(* Logix 5000 project; controller Test vendor 1 type 14 code 92 rev 33.11; software revision 33.00; part 3 of 4 *)
(* tags used below, declared in another part *)
   WLS : Banner_WLS_v4;
   Port_Data : Banner_IOL_Port_v4;
   Port : INT;   // Port Number that device is plugged into.
   Type : SINT;   // 0 = WLS27, 1 = WLS15, 2 = WLF
   Local_Control : DINT;
   Command_Being_Processed : BOOL;
   Update_Archive : BOOL;
   Index_Write_Inprocess : DINT;
   Index_Write_Control : DINT;
   Inprocess_Index : DINT;
   SW_Index : DINT;
   LT_Index : DINT;
   IndexW2 : DINT;
   LTW_Index : DINT;
   G_Index : DINT;
   IndexW3 : DINT;
(* Banner_WLS_Param_v4, continued *)

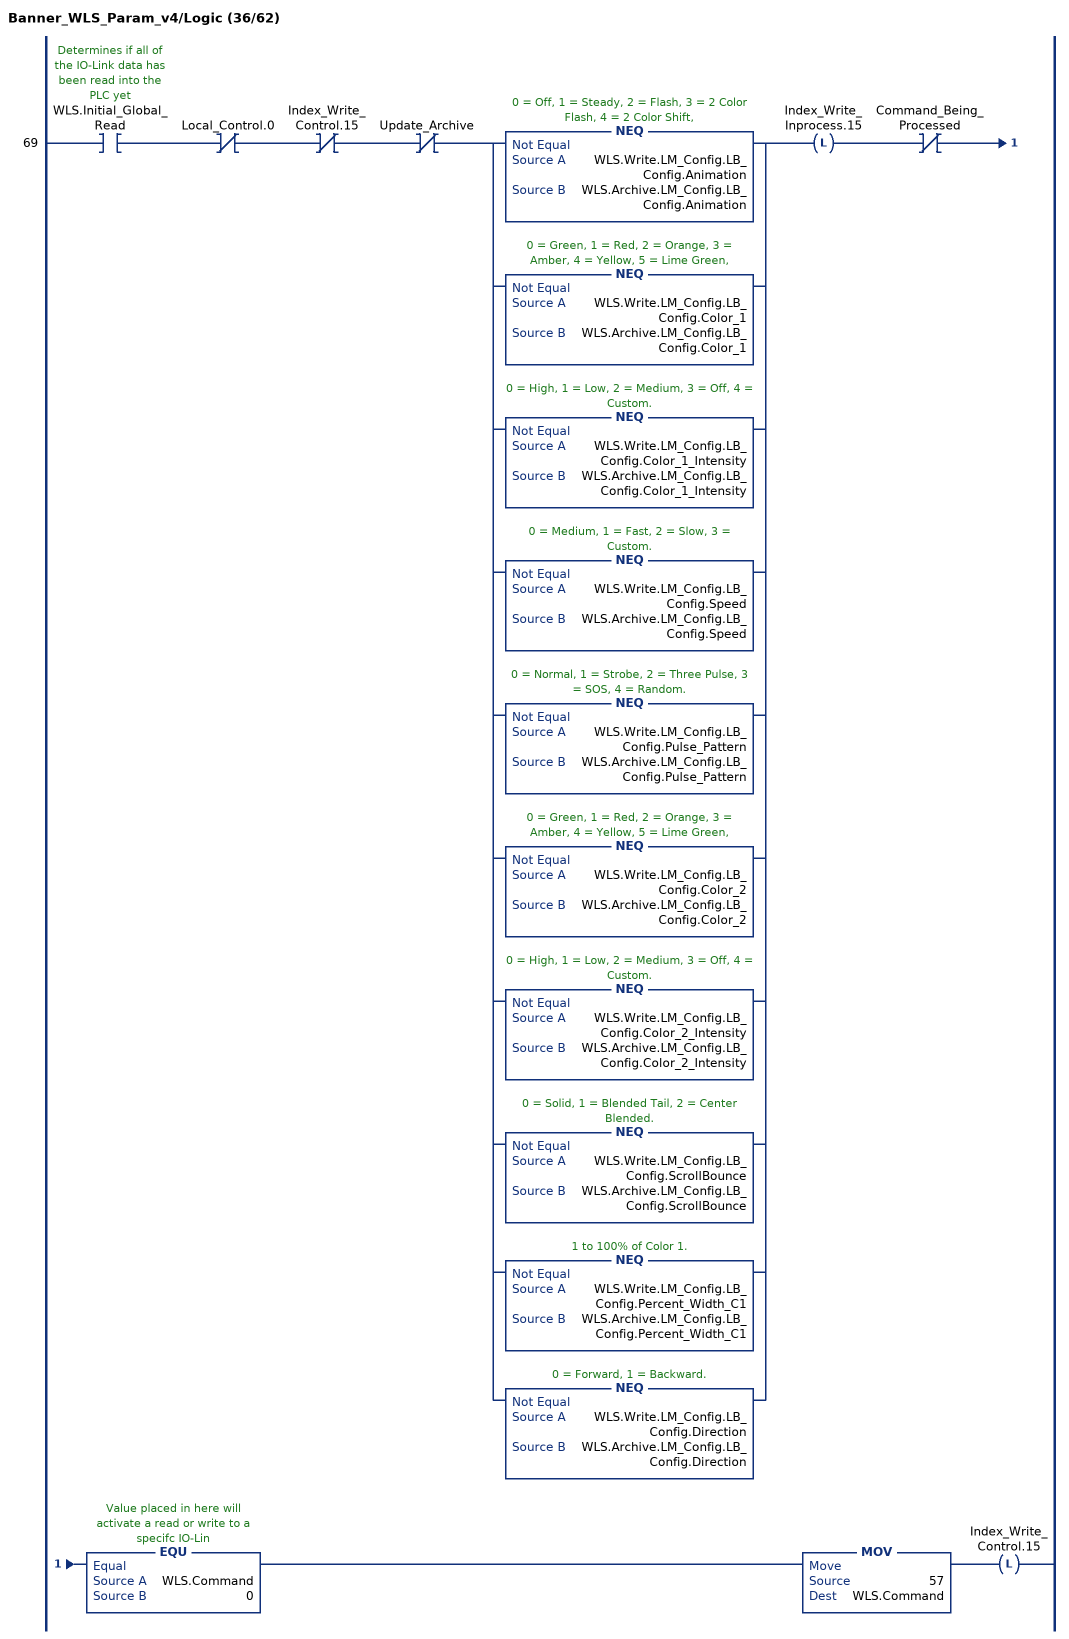
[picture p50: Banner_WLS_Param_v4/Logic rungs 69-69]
   69: XIC(WLS.Initial_Global_Read)XIO(Local_Control.0)XIO(Index_Write_Control.15)XIO(Update_Archive)[NEQ(WLS.Write.LM_Config.LB_Config.Animation,WLS.Archive.LM_Config.LB_Config.Animation) ,NEQ(WLS.Write.LM_Config.LB_Config.Color_1,WLS.Archive.LM_Config.LB_Config.Color_1) ,NEQ(WLS.Write.LM_Config.LB_Config.Color_1_Intensity,WLS.Archive.LM_Config.LB_Config.Color_1_Intensity) ,NEQ(WLS.Write.LM_Config.LB_Config.Speed,WLS.Archive.LM_Config.LB_Config.Speed) ,NEQ(WLS.Write.LM_Config.LB_Config.Pulse_Pattern,WLS.Archive.LM_Config.LB_Config.Pulse_Pattern) ,NEQ(WLS.Write.LM_Config.LB_Config.Color_2,WLS.Archive.LM_Config.LB_Config.Color_2) ,NEQ(WLS.Write.LM_Config.LB_Config.Color_2_Intensity,WLS.Archive.LM_Config.LB_Config.Color_2_Intensity) ,NEQ(WLS.Write.LM_Config.LB_Config.ScrollBounce,WLS.Archive.LM_Config.LB_Config.ScrollBounce) ,NEQ(WLS.Write.LM_Config.LB_Config.Percent_Width_C1,WLS.Archive.LM_Config.LB_Config.Percent_Width_C1) ,NEQ(WLS.Write.LM_Config.LB_Config.Direction,WLS.Archive.LM_Config.LB_Config.Direction) ]OTL(Index_Write_Inprocess.15)XIO(Command_Being_Processed)EQU(WLS.Command,0)MOV(57,WLS.Command)OTL(Index_Write_Control.15);
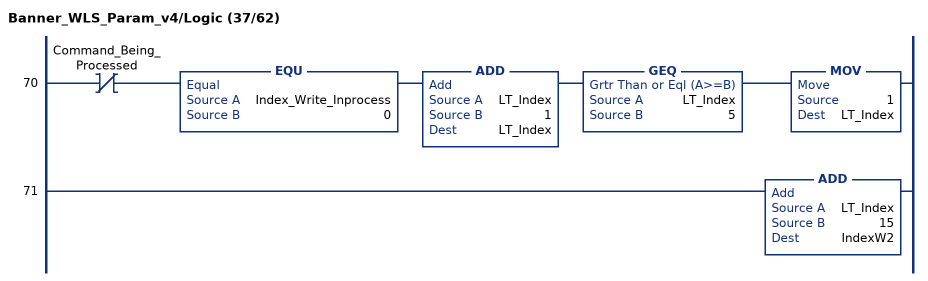
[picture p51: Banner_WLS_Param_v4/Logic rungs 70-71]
   70: XIO(Command_Being_Processed)EQU(Index_Write_Inprocess,0)ADD(LT_Index,1,LT_Index)GEQ(LT_Index,5)MOV(1,LT_Index);
   71: ADD(LT_Index,15,IndexW2);
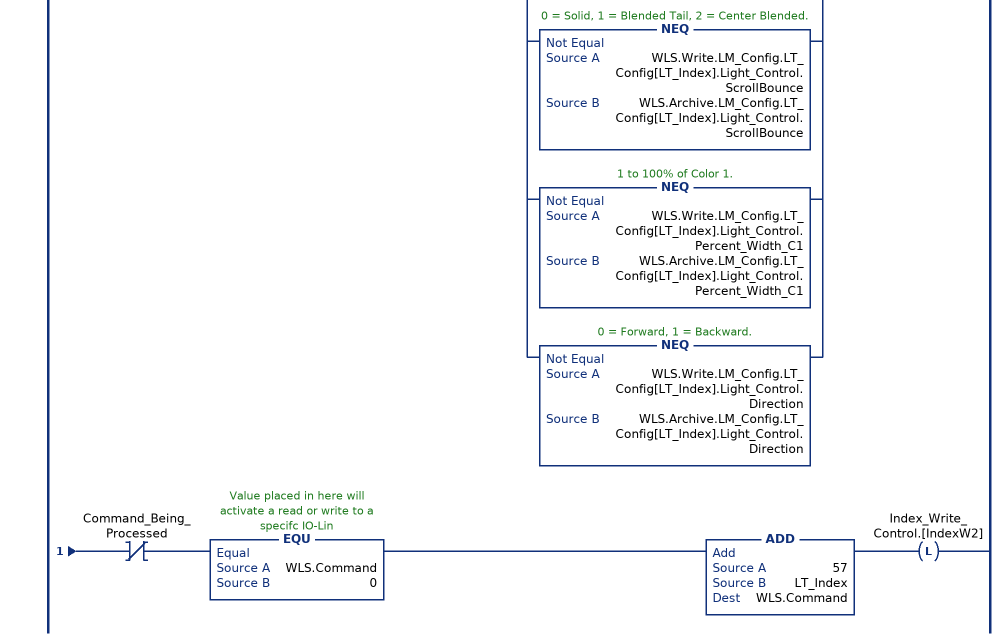
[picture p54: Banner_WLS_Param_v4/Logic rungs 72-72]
   72: XIC(WLS.Initial_Global_Read)XIO(Local_Control.0)XIO(Index_Write_Control.[IndexW2])XIO(Update_Archive)[NEQ(WLS.Write.LM_Config.LT_Config[LT_Index].Threshold_Enable,WLS.Archive.LM_Config.LT_Config[LT_Index].Threshold_Enable) ,NEQ(WLS.Write.LM_Config.LT_Config[LT_Index].Threshold_Value,WLS.Archive.LM_Config.LT_Config[LT_Index].Threshold_Value) ,NEQ(WLS.Write.LM_Config.LT_Config[LT_Index].Threshold_Comparison,WLS.Archive.LM_Config.LT_Config[LT_Index].Threshold_Comparison) ,NEQ(WLS.Write.LM_Config.LT_Config[LT_Index].Threshold_Override,WLS.Archive.LM_Config.LT_Config[LT_Index].Threshold_Override) ,NEQ(WLS.Write.LM_Config.LT_Config[LT_Index].Light_Control.Animation,WLS.Archive.LM_Config.LT_Config[LT_Index].Light_Control.Animation) ,NEQ(WLS.Write.LM_Config.LT_Config[LT_Index].Light_Control.Color_1,WLS.Archive.LM_Config.LT_Config[LT_Index].Light_Control.Color_1) ,NEQ(WLS.Write.LM_Config.LT_Config[LT_Index].Light_Control.Color_1_Intensity,WLS.Archive.LM_Config.LT_Config[LT_Index].Light_Control.Color_1_Intensity) ,NEQ(WLS.Write.LM_Config.LT_Config[LT_Index].Light_Control.Speed,WLS.Archive.LM_Config.LT_Config[LT_Index].Light_Control.Speed) ,NEQ(WLS.Write.LM_Config.LT_Config[LT_Index].Light_Control.Pulse_Pattern,WLS.Archive.LM_Config.LT_Config[LT_Index].Light_Control.Pulse_Pattern) ,NEQ(WLS.Write.LM_Config.LT_Config[LT_Index].Light_Control.Color_2,WLS.Archive.LM_Config.LT_Config[LT_Index].Light_Control.Color_2) ,NEQ(WLS.Write.LM_Config.LT_Config[LT_Index].Light_Control.Color_2_Intensity,WLS.Archive.LM_Config.LT_Config[LT_Index].Light_Control.Color_2_Intensity) ,NEQ(WLS.Write.LM_Config.LT_Config[LT_Index].Light_Control.ScrollBounce,WLS.Archive.LM_Config.LT_Config[LT_Index].Light_Control.ScrollBounce) ,NEQ(WLS.Write.LM_Config.LT_Config[LT_Index].Light_Control.Percent_Width_C1,WLS.Archive.LM_Config.LT_Config[LT_Index].Light_Control.Percent_Width_C1) ,NEQ(WLS.Write.LM_Config.LT_Config[LT_Index].Light_Control.Direction,WLS.Archive.LM_Config.LT_Config[LT_Index].Light_Control.Direction) ]OTL(Index_Write_Inprocess.[IndexW2])XIO(Command_Being_Processed)EQU(WLS.Command,0)ADD(57,LT_Index,WLS.Command)OTL(Index_Write_Control.[IndexW2]);
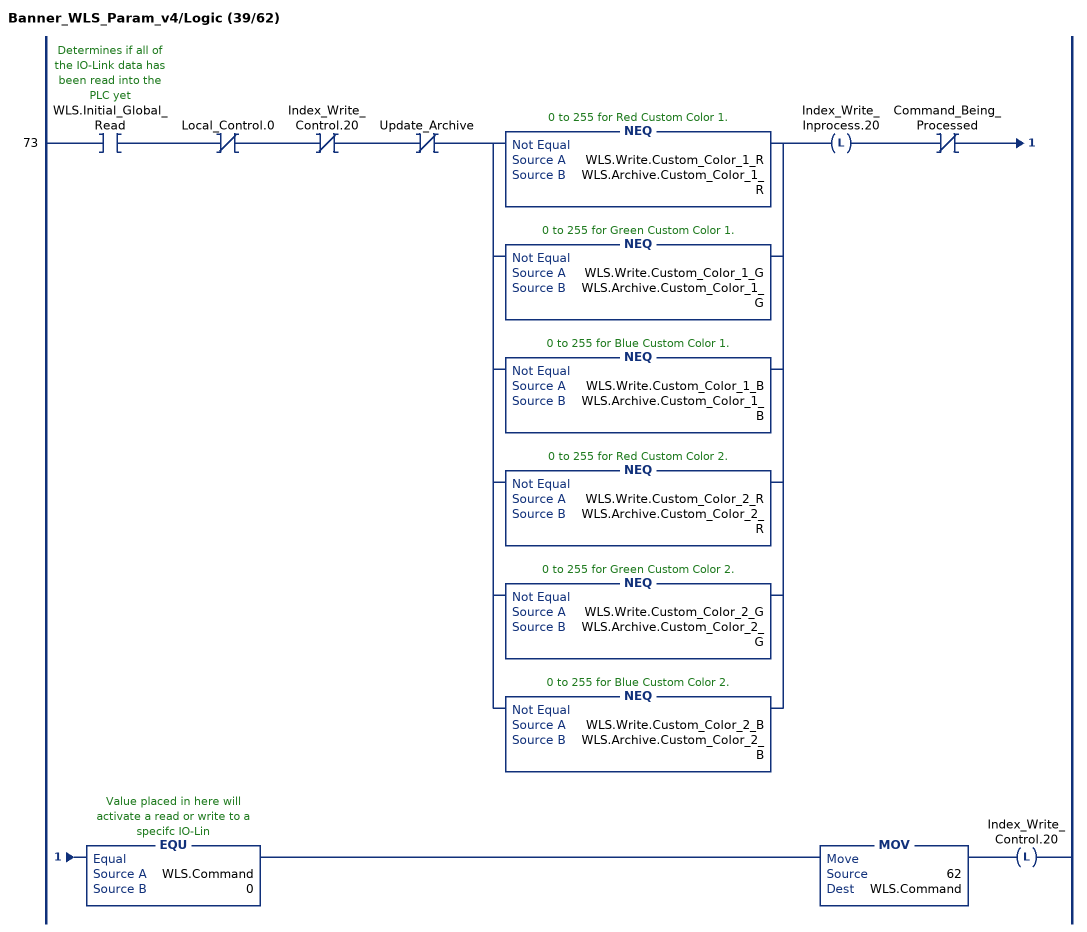
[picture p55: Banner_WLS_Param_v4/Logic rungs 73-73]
   73: XIC(WLS.Initial_Global_Read)XIO(Local_Control.0)XIO(Index_Write_Control.20)XIO(Update_Archive)[NEQ(WLS.Write.Custom_Color_1_R,WLS.Archive.Custom_Color_1_R) ,NEQ(WLS.Write.Custom_Color_1_G,WLS.Archive.Custom_Color_1_G) ,NEQ(WLS.Write.Custom_Color_1_B,WLS.Archive.Custom_Color_1_B) ,NEQ(WLS.Write.Custom_Color_2_R,WLS.Archive.Custom_Color_2_R) ,NEQ(WLS.Write.Custom_Color_2_G,WLS.Archive.Custom_Color_2_G) ,NEQ(WLS.Write.Custom_Color_2_B,WLS.Archive.Custom_Color_2_B) ]OTL(Index_Write_Inprocess.20)XIO(Command_Being_Processed)EQU(WLS.Command,0)MOV(62,WLS.Command)OTL(Index_Write_Control.20);
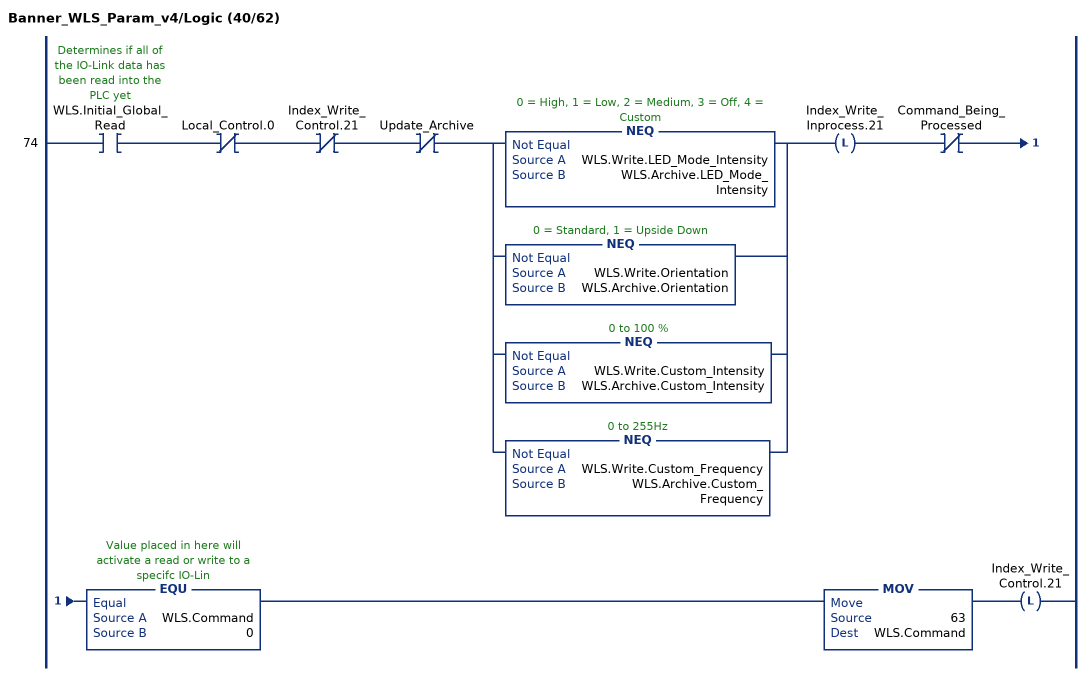
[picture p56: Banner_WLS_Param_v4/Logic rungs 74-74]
   74: XIC(WLS.Initial_Global_Read)XIO(Local_Control.0)XIO(Index_Write_Control.21)XIO(Update_Archive)[NEQ(WLS.Write.LED_Mode_Intensity,WLS.Archive.LED_Mode_Intensity) ,NEQ(WLS.Write.Orientation,WLS.Archive.Orientation) ,NEQ(WLS.Write.Custom_Intensity,WLS.Archive.Custom_Intensity) ,NEQ(WLS.Write.Custom_Frequency,WLS.Archive.Custom_Frequency) ]OTL(Index_Write_Inprocess.21)XIO(Command_Being_Processed)EQU(WLS.Command,0)MOV(63,WLS.Command)OTL(Index_Write_Control.21);
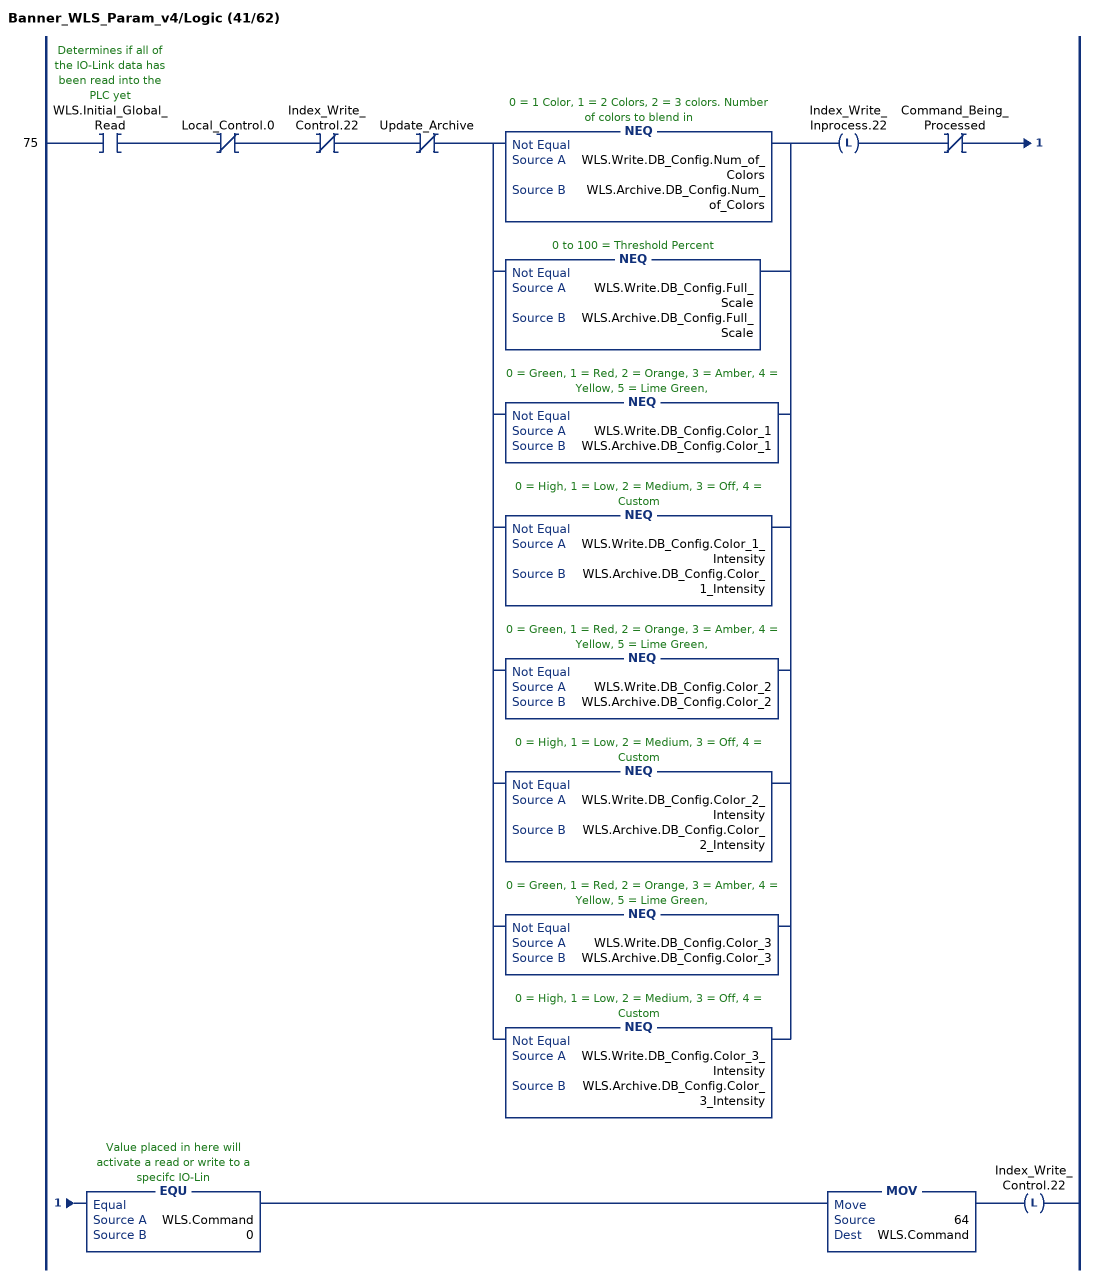
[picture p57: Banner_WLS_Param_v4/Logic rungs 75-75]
   75: XIC(WLS.Initial_Global_Read)XIO(Local_Control.0)XIO(Index_Write_Control.22)XIO(Update_Archive)[NEQ(WLS.Write.DB_Config.Num_of_Colors,WLS.Archive.DB_Config.Num_of_Colors) ,NEQ(WLS.Write.DB_Config.Full_Scale,WLS.Archive.DB_Config.Full_Scale) ,NEQ(WLS.Write.DB_Config.Color_1,WLS.Archive.DB_Config.Color_1) ,NEQ(WLS.Write.DB_Config.Color_1_Intensity,WLS.Archive.DB_Config.Color_1_Intensity) ,NEQ(WLS.Write.DB_Config.Color_2,WLS.Archive.DB_Config.Color_2) ,NEQ(WLS.Write.DB_Config.Color_2_Intensity,WLS.Archive.DB_Config.Color_2_Intensity) ,NEQ(WLS.Write.DB_Config.Color_3,WLS.Archive.DB_Config.Color_3) ,NEQ(WLS.Write.DB_Config.Color_3_Intensity,WLS.Archive.DB_Config.Color_3_Intensity) ]OTL(Index_Write_Inprocess.22)XIO(Command_Being_Processed)EQU(WLS.Command,0)MOV(64,WLS.Command)OTL(Index_Write_Control.22);
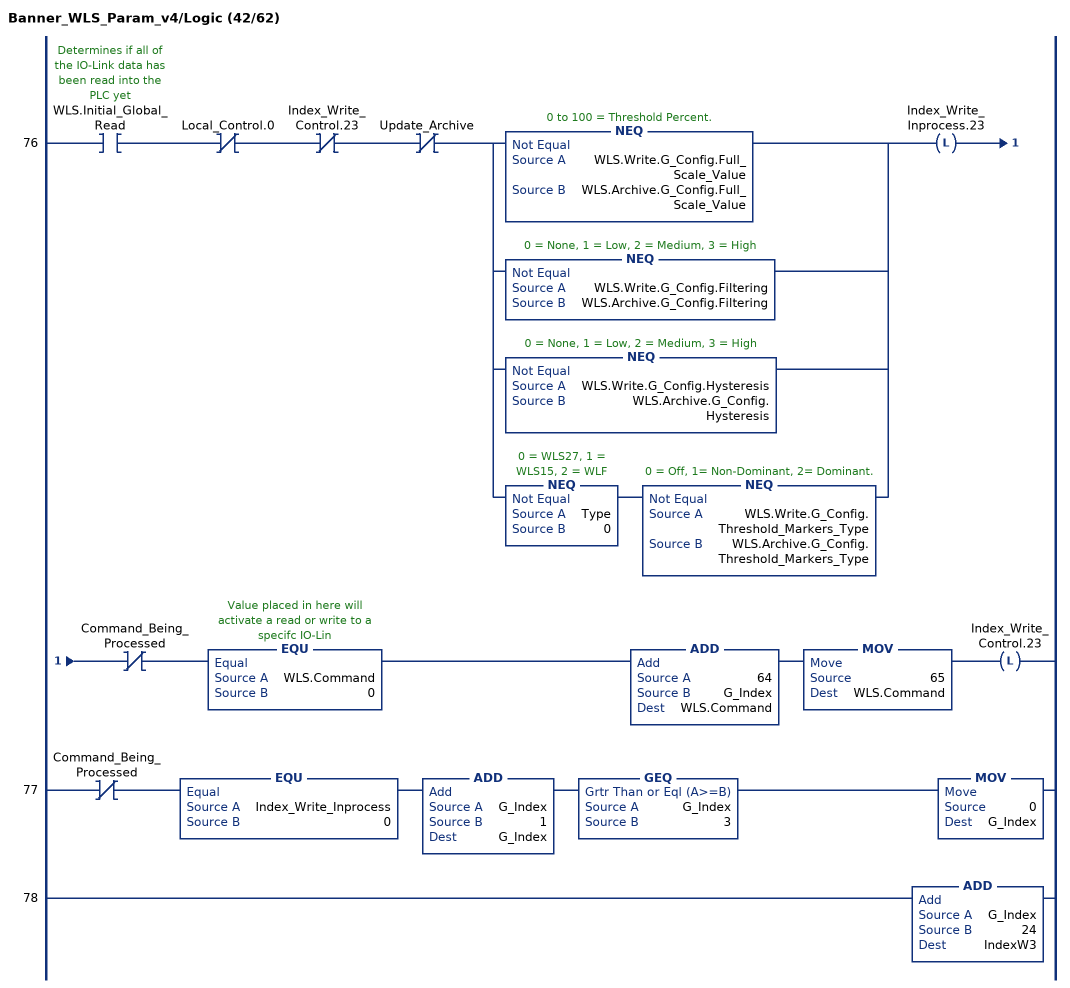
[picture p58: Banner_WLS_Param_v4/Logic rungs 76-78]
   76: XIC(WLS.Initial_Global_Read)XIO(Local_Control.0)XIO(Index_Write_Control.23)XIO(Update_Archive)[NEQ(WLS.Write.G_Config.Full_Scale_Value,WLS.Archive.G_Config.Full_Scale_Value) ,NEQ(WLS.Write.G_Config.Filtering,WLS.Archive.G_Config.Filtering) ,NEQ(WLS.Write.G_Config.Hysteresis,WLS.Archive.G_Config.Hysteresis) ,NEQ(Type,0) NEQ(WLS.Write.G_Config.Threshold_Markers_Type,WLS.Archive.G_Config.Threshold_Markers_Type) ]OTL(Index_Write_Inprocess.23)XIO(Command_Being_Processed)EQU(WLS.Command,0)ADD(64,G_Index,WLS.Command)MOV(65,WLS.Command)OTL(Index_Write_Control.23);
   77: XIO(Command_Being_Processed)EQU(Index_Write_Inprocess,0)ADD(G_Index,1,G_Index)GEQ(G_Index,3)MOV(0,G_Index);
   78: ADD(G_Index,24,IndexW3);
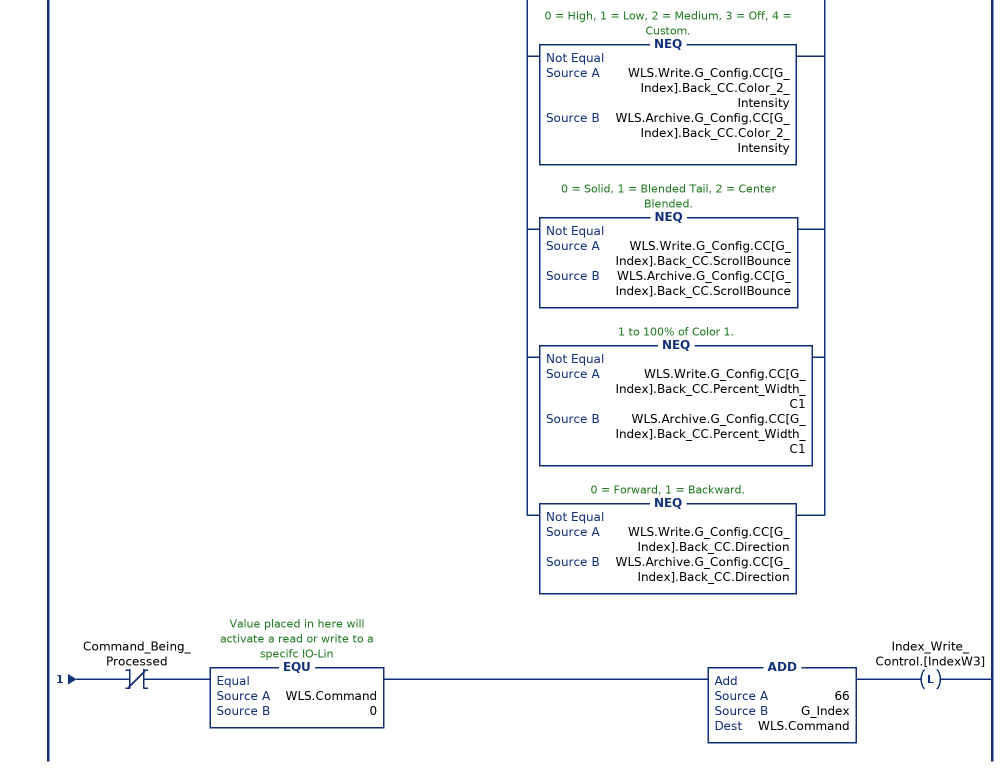
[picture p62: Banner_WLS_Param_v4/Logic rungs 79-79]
   79: XIC(WLS.Initial_Global_Read)XIO(Local_Control.0)XIO(Index_Write_Control.[IndexW3])XIO(Update_Archive)[NEQ(WLS.Write.G_Config.CC[G_Index].Threshold_Enable,WLS.Archive.G_Config.CC[G_Index].Threshold_Enable) ,NEQ(WLS.Write.G_Config.CC[G_Index].Threshold_Value_Percent,WLS.Archive.G_Config.CC[G_Index].Threshold_Value_Percent) ,NEQ(WLS.Write.G_Config.CC[G_Index].Threshold_Comparison,WLS.Archive.G_Config.CC[G_Index].Threshold_Comparison) ,NEQ(WLS.Write.G_Config.CC[G_Index].Percent_Width_of_Main_Segment,WLS.Archive.G_Config.CC[G_Index].Percent_Width_of_Main_Segment) ,NEQ(WLS.Write.G_Config.CC[G_Index].Main_CC.Animation,WLS.Archive.G_Config.CC[G_Index].Main_CC.Animation) ,NEQ(WLS.Write.G_Config.CC[G_Index].Main_CC.Color_1,WLS.Archive.G_Config.CC[G_Index].Main_CC.Color_1) ,NEQ(WLS.Write.G_Config.CC[G_Index].Main_CC.Color_1_Intensity,WLS.Archive.G_Config.CC[G_Index].Main_CC.Color_1_Intensity) ,NEQ(WLS.Write.G_Config.CC[G_Index].Main_CC.Speed,WLS.Archive.G_Config.CC[G_Index].Main_CC.Speed) ,NEQ(WLS.Write.G_Config.CC[G_Index].Main_CC.Pulse_Pattern,WLS.Archive.G_Config.CC[G_Index].Main_CC.Pulse_Pattern) ,NEQ(WLS.Write.G_Config.CC[G_Index].Main_CC.Color_2,WLS.Archive.G_Config.CC[G_Index].Main_CC.Color_2) ,NEQ(WLS.Write.G_Config.CC[G_Index].Main_CC.Color_2_Intensity,WLS.Archive.G_Config.CC[G_Index].Main_CC.Color_2_Intensity) ,NEQ(WLS.Write.G_Config.CC[G_Index].Main_CC.ScrollBounce,WLS.Archive.G_Config.CC[G_Index].Main_CC.ScrollBounce) ,NEQ(WLS.Write.G_Config.CC[G_Index].Main_CC.Percent_Width_C1,WLS.Archive.G_Config.CC[G_Index].Main_CC.Percent_Width_C1) ,NEQ(WLS.Write.G_Config.CC[G_Index].Main_CC.Direction,WLS.Archive.G_Config.CC[G_Index].Main_CC.Direction) ,NEQ(WLS.Write.G_Config.CC[G_Index].Back_CC.Animation,WLS.Archive.G_Config.CC[G_Index].Back_CC.Animation) ,NEQ(WLS.Write.G_Config.CC[G_Index].Back_CC.Color_1,WLS.Archive.G_Config.CC[G_Index].Back_CC.Color_1) ,NEQ(WLS.Write.G_Config.CC[G_Index].Back_CC.Color_1_Intensity,WLS.Archive.G_Config.CC[G_Index].Back_CC.Color_1_Intensity) ,NEQ(WLS.Write.G_Config.CC[G_Index].Back_CC.Speed,WLS.Archive.G_Config.CC[0].Back_CC.Speed) ,NEQ(WLS.Write.G_Config.CC[G_Index].Back_CC.Pulse_Pattern,WLS.Archive.G_Config.CC[G_Index].Back_CC.Pulse_Pattern) ,NEQ(WLS.Write.G_Config.CC[G_Index].Back_CC.Color_2,WLS.Archive.G_Config.CC[G_Index].Back_CC.Color_2) ,NEQ(WLS.Write.G_Config.CC[G_Index].Back_CC.Color_2_Intensity,WLS.Archive.G_Config.CC[G_Index].Back_CC.Color_2_Intensity) ,NEQ(WLS.Write.G_Config.CC[G_Index].Back_CC.ScrollBounce,WLS.Archive.G_Config.CC[G_Index].Back_CC.ScrollBounce) ,NEQ(WLS.Write.G_Config.CC[G_Index].Back_CC.Percent_Width_C1,WLS.Archive.G_Config.CC[G_Index].Back_CC.Percent_Width_C1) ,NEQ(WLS.Write.G_Config.CC[G_Index].Back_CC.Direction,WLS.Archive.G_Config.CC[G_Index].Back_CC.Direction) ]OTL(Index_Write_Inprocess.[IndexW3])XIO(Command_Being_Processed)EQU(WLS.Command,0)ADD(66,G_Index,WLS.Command)OTL(Index_Write_Control.[IndexW3]);
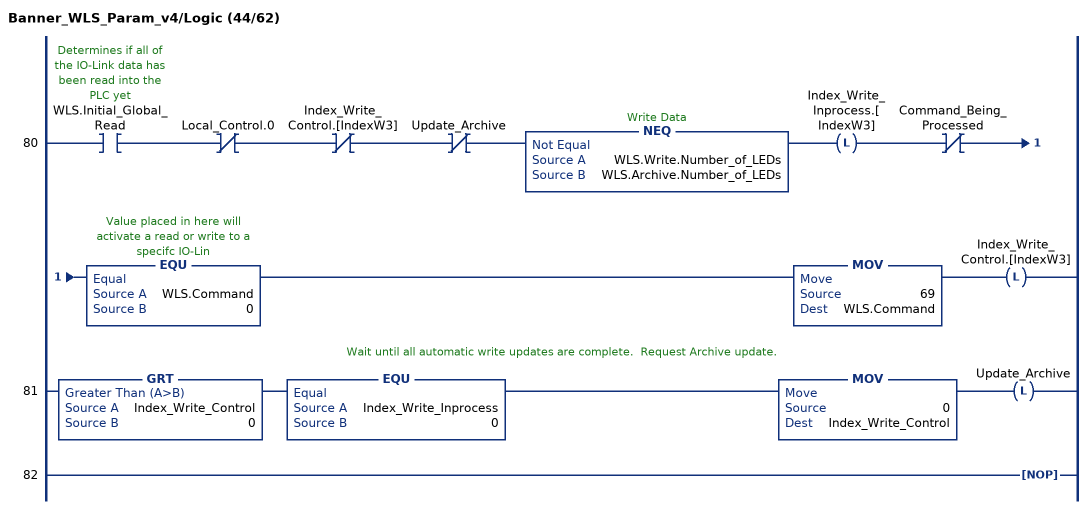
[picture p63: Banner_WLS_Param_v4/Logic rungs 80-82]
   80: XIC(WLS.Initial_Global_Read)XIO(Local_Control.0)XIO(Index_Write_Control.[IndexW3])XIO(Update_Archive)NEQ(WLS.Write.Number_of_LEDs,WLS.Archive.Number_of_LEDs)OTL(Index_Write_Inprocess.[IndexW3])XIO(Command_Being_Processed)EQU(WLS.Command,0)MOV(69,WLS.Command)OTL(Index_Write_Control.[IndexW3]);
   // Wait until all automatic write updates are complete.  Request Archive update.
   81: GRT(Index_Write_Control,0)EQU(Index_Write_Inprocess,0)MOV(0,Index_Write_Control)OTL(Update_Archive);
   82: NOP();
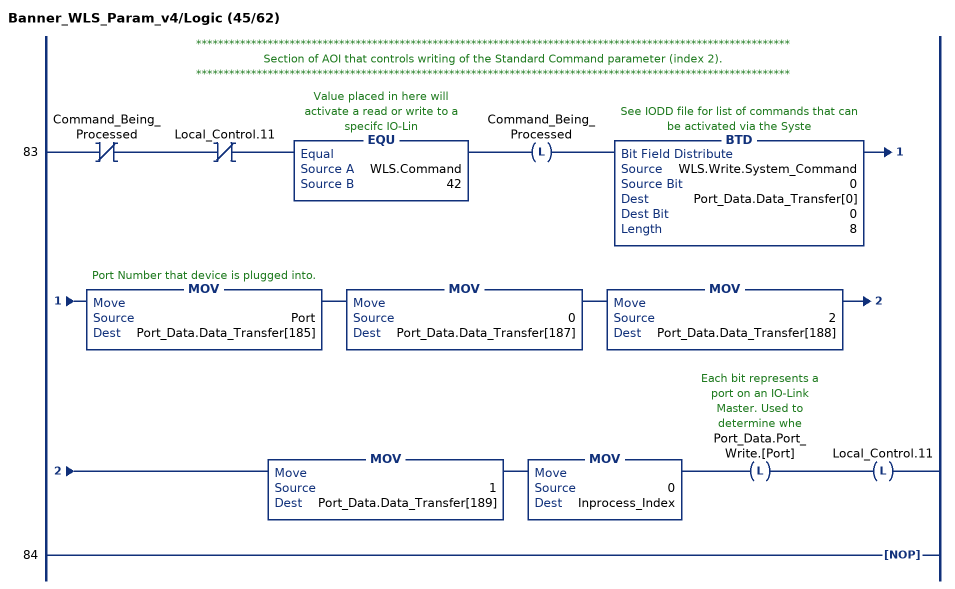
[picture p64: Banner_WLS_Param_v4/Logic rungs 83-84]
   // ************************************************************************************************************
   // Section of AOI that controls writing of the Standard Command parameter (index 2).
   // ************************************************************************************************************
   83: XIO(Command_Being_Processed)XIO(Local_Control.11)EQU(WLS.Command,42)OTL(Command_Being_Processed)BTD(WLS.Write.System_Command,0,Port_Data.Data_Transfer[0],0,8)MOV(Port,Port_Data.Data_Transfer[185])MOV(0,Port_Data.Data_Transfer[187])MOV(2,Port_Data.Data_Transfer[188])MOV(1,Port_Data.Data_Transfer[189])MOV(0,Inprocess_Index)OTL(Port_Data.Port_Write.[Port])OTL(Local_Control.11);
   84: NOP();
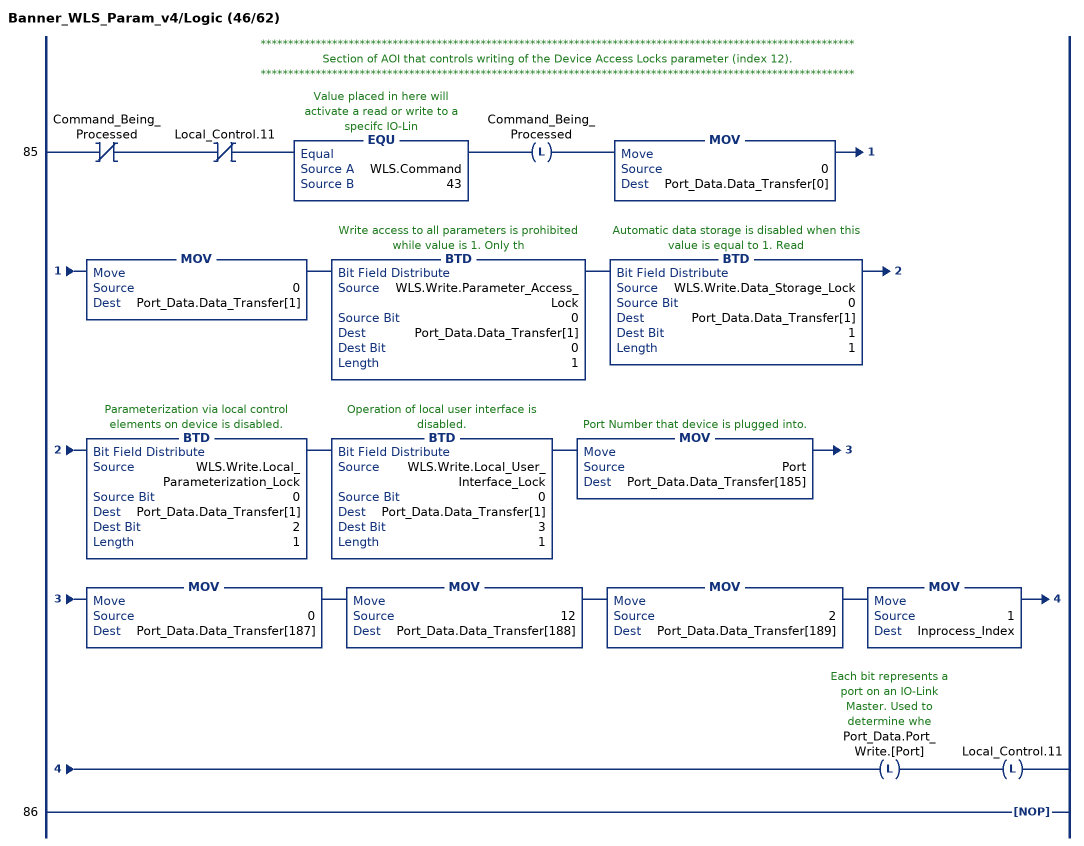
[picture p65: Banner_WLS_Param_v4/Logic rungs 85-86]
   // ************************************************************************************************************
   // Section of AOI that controls writing of the Device Access Locks parameter (index 12).
   // ************************************************************************************************************
   85: XIO(Command_Being_Processed)XIO(Local_Control.11)EQU(WLS.Command,43)OTL(Command_Being_Processed)MOV(0,Port_Data.Data_Transfer[0])MOV(0,Port_Data.Data_Transfer[1])BTD(WLS.Write.Parameter_Access_Lock,0,Port_Data.Data_Transfer[1],0,1)BTD(WLS.Write.Data_Storage_Lock,0,Port_Data.Data_Transfer[1],1,1)BTD(WLS.Write.Local_Parameterization_Lock,0,Port_Data.Data_Transfer[1],2,1)BTD(WLS.Write.Local_User_Interface_Lock,0,Port_Data.Data_Transfer[1],3,1)MOV(Port,Port_Data.Data_Transfer[185])MOV(0,Port_Data.Data_Transfer[187])MOV(12,Port_Data.Data_Transfer[188])MOV(2,Port_Data.Data_Transfer[189])MOV(1,Inprocess_Index)OTL(Port_Data.Port_Write.[Port])OTL(Local_Control.11);
   86: NOP();
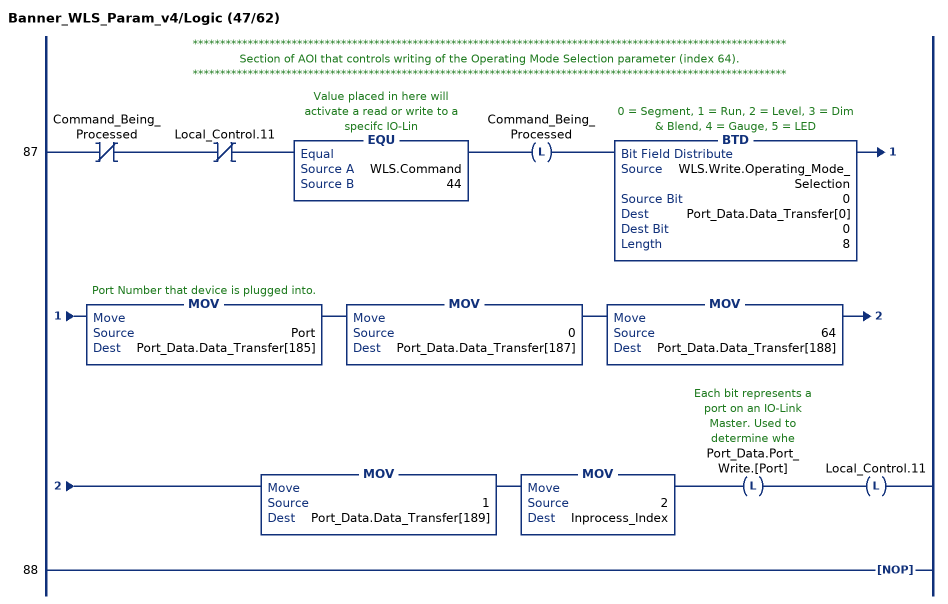
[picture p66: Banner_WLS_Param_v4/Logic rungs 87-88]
   // ************************************************************************************************************
   // Section of AOI that controls writing of the Operating Mode Selection parameter (index 64).
   // ************************************************************************************************************
   87: XIO(Command_Being_Processed)XIO(Local_Control.11)EQU(WLS.Command,44)OTL(Command_Being_Processed)BTD(WLS.Write.Operating_Mode_Selection,0,Port_Data.Data_Transfer[0],0,8)MOV(Port,Port_Data.Data_Transfer[185])MOV(0,Port_Data.Data_Transfer[187])MOV(64,Port_Data.Data_Transfer[188])MOV(1,Port_Data.Data_Transfer[189])MOV(2,Inprocess_Index)OTL(Port_Data.Port_Write.[Port])OTL(Local_Control.11);
   88: NOP();
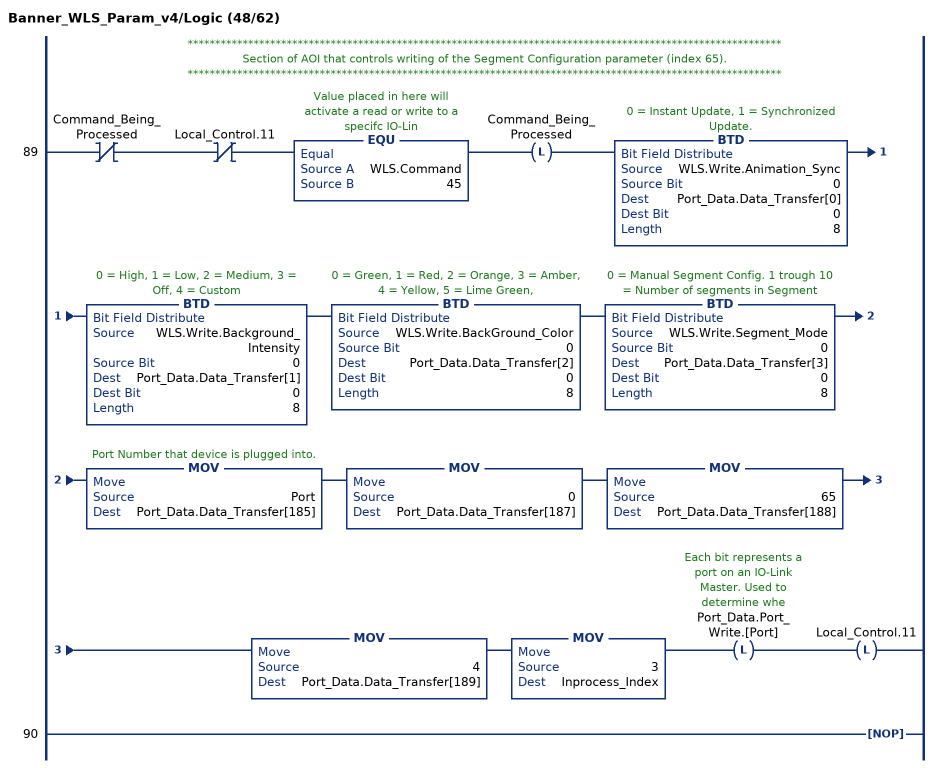
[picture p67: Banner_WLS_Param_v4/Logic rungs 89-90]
   // ************************************************************************************************************
   // Section of AOI that controls writing of the Segment Configuration parameter (index 65).
   // ************************************************************************************************************
   89: XIO(Command_Being_Processed)XIO(Local_Control.11)EQU(WLS.Command,45)OTL(Command_Being_Processed)BTD(WLS.Write.Animation_Sync,0,Port_Data.Data_Transfer[0],0,8)BTD(WLS.Write.Background_Intensity,0,Port_Data.Data_Transfer[1],0,8)BTD(WLS.Write.BackGround_Color,0,Port_Data.Data_Transfer[2],0,8)BTD(WLS.Write.Segment_Mode,0,Port_Data.Data_Transfer[3],0,8)MOV(Port,Port_Data.Data_Transfer[185])MOV(0,Port_Data.Data_Transfer[187])MOV(65,Port_Data.Data_Transfer[188])MOV(4,Port_Data.Data_Transfer[189])MOV(3,Inprocess_Index)OTL(Port_Data.Port_Write.[Port])OTL(Local_Control.11);
   90: NOP();
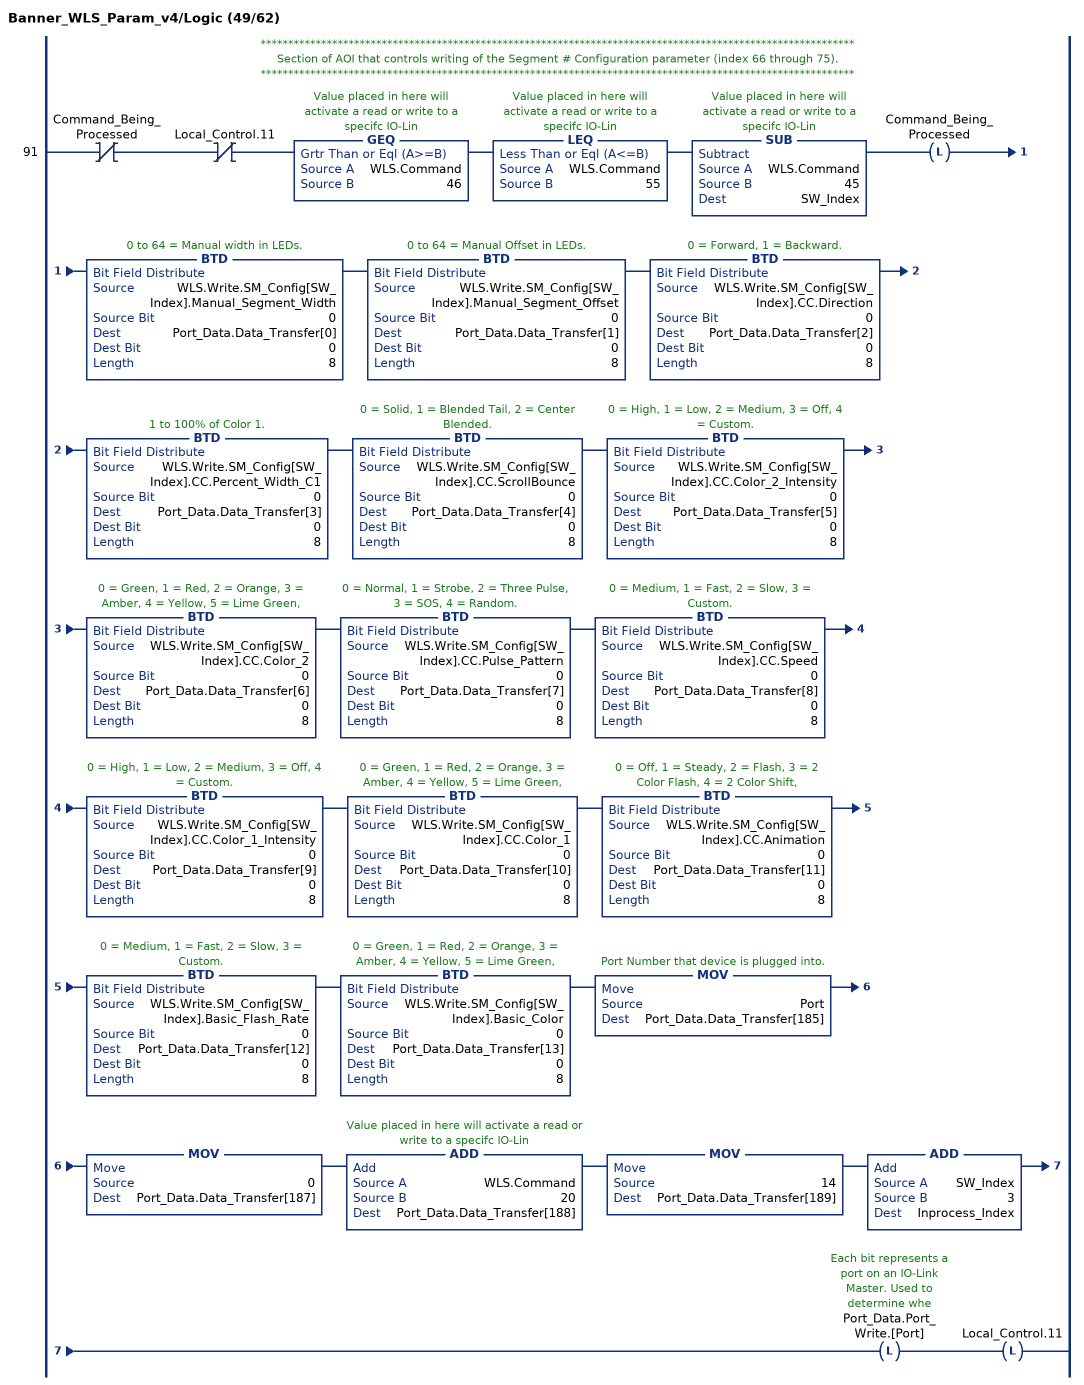
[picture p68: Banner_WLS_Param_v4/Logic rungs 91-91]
   // ************************************************************************************************************
   // Section of AOI that controls writing of the Segment # Configuration parameter (index 66 through 75).
   // ************************************************************************************************************
   91: XIO(Command_Being_Processed)XIO(Local_Control.11)GEQ(WLS.Command,46)LEQ(WLS.Command,55)SUB(WLS.Command,45,SW_Index)OTL(Command_Being_Processed)BTD(WLS.Write.SM_Config[SW_Index].Manual_Segment_Width,0,Port_Data.Data_Transfer[0],0,8)BTD(WLS.Write.SM_Config[SW_Index].Manual_Segment_Offset,0,Port_Data.Data_Transfer[1],0,8)BTD(WLS.Write.SM_Config[SW_Index].CC.Direction,0,Port_Data.Data_Transfer[2],0,8)BTD(WLS.Write.SM_Config[SW_Index].CC.Percent_Width_C1,0,Port_Data.Data_Transfer[3],0,8)BTD(WLS.Write.SM_Config[SW_Index].CC.ScrollBounce,0,Port_Data.Data_Transfer[4],0,8)BTD(WLS.Write.SM_Config[SW_Index].CC.Color_2_Intensity,0,Port_Data.Data_Transfer[5],0,8)BTD(WLS.Write.SM_Config[SW_Index].CC.Color_2,0,Port_Data.Data_Transfer[6],0,8)BTD(WLS.Write.SM_Config[SW_Index].CC.Pulse_Pattern,0,Port_Data.Data_Transfer[7],0,8)BTD(WLS.Write.SM_Config[SW_Index].CC.Speed,0,Port_Data.Data_Transfer[8],0,8)BTD(WLS.Write.SM_Config[SW_Index].CC.Color_1_Intensity,0,Port_Data.Data_Transfer[9],0,8)BTD(WLS.Write.SM_Config[SW_Index].CC.Color_1,0,Port_Data.Data_Transfer[10],0,8)BTD(WLS.Write.SM_Config[SW_Index].CC.Animation,0,Port_Data.Data_Transfer[11],0,8)BTD(WLS.Write.SM_Config[SW_Index].Basic_Flash_Rate,0,Port_Data.Data_Transfer[12],0,8)BTD(WLS.Write.SM_Config[SW_Index].Basic_Color,0,Port_Data.Data_Transfer[13],0,8)MOV(Port,Port_Data.Data_Transfer[185])MOV(0,Port_Data.Data_Transfer[187])ADD(WLS.Command,20,Port_Data.Data_Transfer[188])MOV(14,Port_Data.Data_Transfer[189])ADD(SW_Index,3,Inprocess_Index)OTL(Port_Data.Port_Write.[Port])OTL(Local_Control.11);
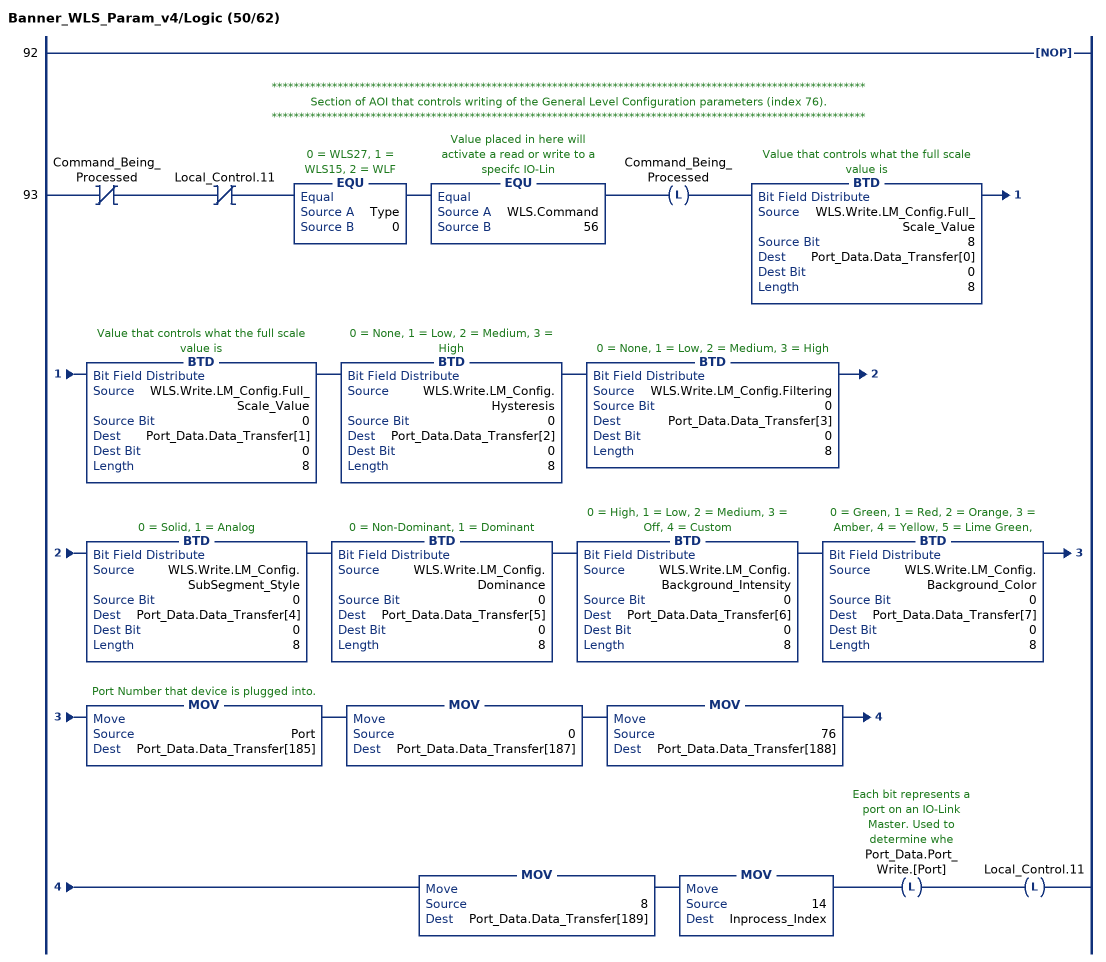
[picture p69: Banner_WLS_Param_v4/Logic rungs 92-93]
   92: NOP();
   // ************************************************************************************************************
   // Section of AOI that controls writing of the General Level Configuration parameters (index 76).
   // ************************************************************************************************************
   93: XIO(Command_Being_Processed)XIO(Local_Control.11)EQU(Type,0)EQU(WLS.Command,56)OTL(Command_Being_Processed)BTD(WLS.Write.LM_Config.Full_Scale_Value,8,Port_Data.Data_Transfer[0],0,8)BTD(WLS.Write.LM_Config.Full_Scale_Value,0,Port_Data.Data_Transfer[1],0,8)BTD(WLS.Write.LM_Config.Hysteresis,0,Port_Data.Data_Transfer[2],0,8)BTD(WLS.Write.LM_Config.Filtering,0,Port_Data.Data_Transfer[3],0,8)BTD(WLS.Write.LM_Config.SubSegment_Style,0,Port_Data.Data_Transfer[4],0,8)BTD(WLS.Write.LM_Config.Dominance,0,Port_Data.Data_Transfer[5],0,8)BTD(WLS.Write.LM_Config.Background_Intensity,0,Port_Data.Data_Transfer[6],0,8)BTD(WLS.Write.LM_Config.Background_Color,0,Port_Data.Data_Transfer[7],0,8)MOV(Port,Port_Data.Data_Transfer[185])MOV(0,Port_Data.Data_Transfer[187])MOV(76,Port_Data.Data_Transfer[188])MOV(8,Port_Data.Data_Transfer[189])MOV(14,Inprocess_Index)OTL(Port_Data.Port_Write.[Port])OTL(Local_Control.11);
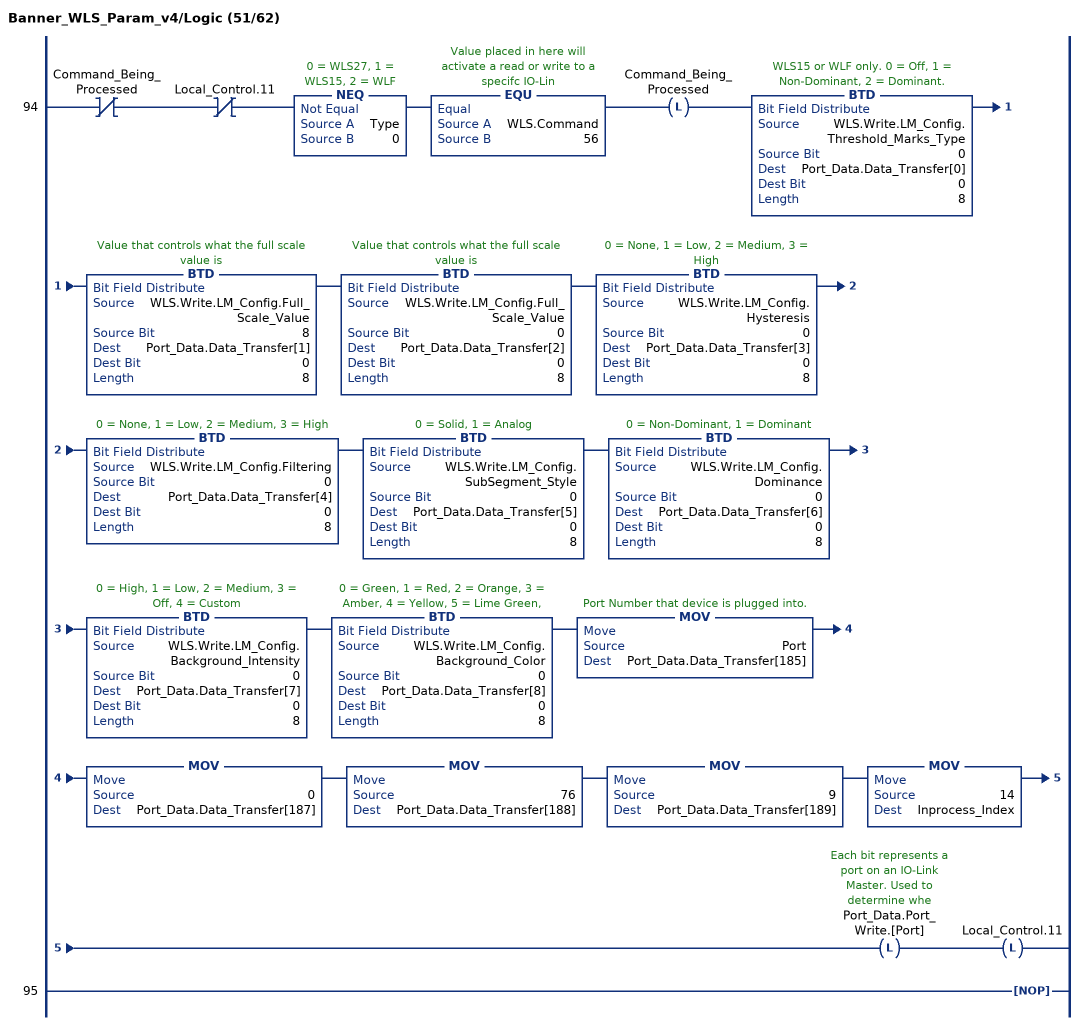
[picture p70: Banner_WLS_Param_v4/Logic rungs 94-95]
   94: XIO(Command_Being_Processed)XIO(Local_Control.11)NEQ(Type,0)EQU(WLS.Command,56)OTL(Command_Being_Processed)BTD(WLS.Write.LM_Config.Threshold_Marks_Type,0,Port_Data.Data_Transfer[0],0,8)BTD(WLS.Write.LM_Config.Full_Scale_Value,8,Port_Data.Data_Transfer[1],0,8)BTD(WLS.Write.LM_Config.Full_Scale_Value,0,Port_Data.Data_Transfer[2],0,8)BTD(WLS.Write.LM_Config.Hysteresis,0,Port_Data.Data_Transfer[3],0,8)BTD(WLS.Write.LM_Config.Filtering,0,Port_Data.Data_Transfer[4],0,8)BTD(WLS.Write.LM_Config.SubSegment_Style,0,Port_Data.Data_Transfer[5],0,8)BTD(WLS.Write.LM_Config.Dominance,0,Port_Data.Data_Transfer[6],0,8)BTD(WLS.Write.LM_Config.Background_Intensity,0,Port_Data.Data_Transfer[7],0,8)BTD(WLS.Write.LM_Config.Background_Color,0,Port_Data.Data_Transfer[8],0,8)MOV(Port,Port_Data.Data_Transfer[185])MOV(0,Port_Data.Data_Transfer[187])MOV(76,Port_Data.Data_Transfer[188])MOV(9,Port_Data.Data_Transfer[189])MOV(14,Inprocess_Index)OTL(Port_Data.Port_Write.[Port])OTL(Local_Control.11);
   95: NOP();
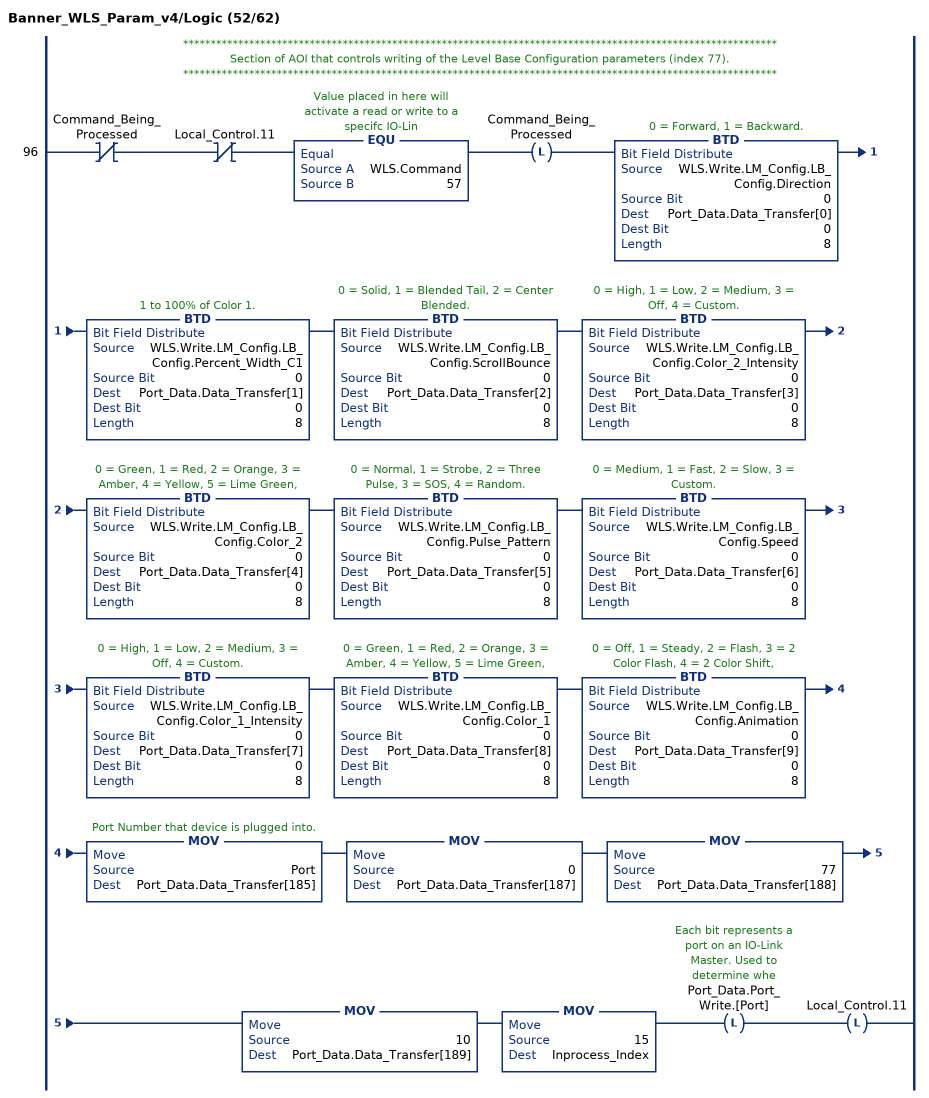
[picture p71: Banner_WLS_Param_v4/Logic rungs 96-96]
   // ************************************************************************************************************
   // Section of AOI that controls writing of the Level Base Configuration parameters (index 77).
   // ************************************************************************************************************
   96: XIO(Command_Being_Processed)XIO(Local_Control.11)EQU(WLS.Command,57)OTL(Command_Being_Processed)BTD(WLS.Write.LM_Config.LB_Config.Direction,0,Port_Data.Data_Transfer[0],0,8)BTD(WLS.Write.LM_Config.LB_Config.Percent_Width_C1,0,Port_Data.Data_Transfer[1],0,8)BTD(WLS.Write.LM_Config.LB_Config.ScrollBounce,0,Port_Data.Data_Transfer[2],0,8)BTD(WLS.Write.LM_Config.LB_Config.Color_2_Intensity,0,Port_Data.Data_Transfer[3],0,8)BTD(WLS.Write.LM_Config.LB_Config.Color_2,0,Port_Data.Data_Transfer[4],0,8)BTD(WLS.Write.LM_Config.LB_Config.Pulse_Pattern,0,Port_Data.Data_Transfer[5],0,8)BTD(WLS.Write.LM_Config.LB_Config.Speed,0,Port_Data.Data_Transfer[6],0,8)BTD(WLS.Write.LM_Config.LB_Config.Color_1_Intensity,0,Port_Data.Data_Transfer[7],0,8)BTD(WLS.Write.LM_Config.LB_Config.Color_1,0,Port_Data.Data_Transfer[8],0,8)BTD(WLS.Write.LM_Config.LB_Config.Animation,0,Port_Data.Data_Transfer[9],0,8)MOV(Port,Port_Data.Data_Transfer[185])MOV(0,Port_Data.Data_Transfer[187])MOV(77,Port_Data.Data_Transfer[188])MOV(10,Port_Data.Data_Transfer[189])MOV(15,Inprocess_Index)OTL(Port_Data.Port_Write.[Port])OTL(Local_Control.11);
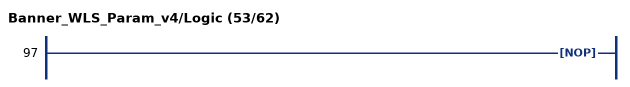
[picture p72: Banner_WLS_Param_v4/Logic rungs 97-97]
   97: NOP();
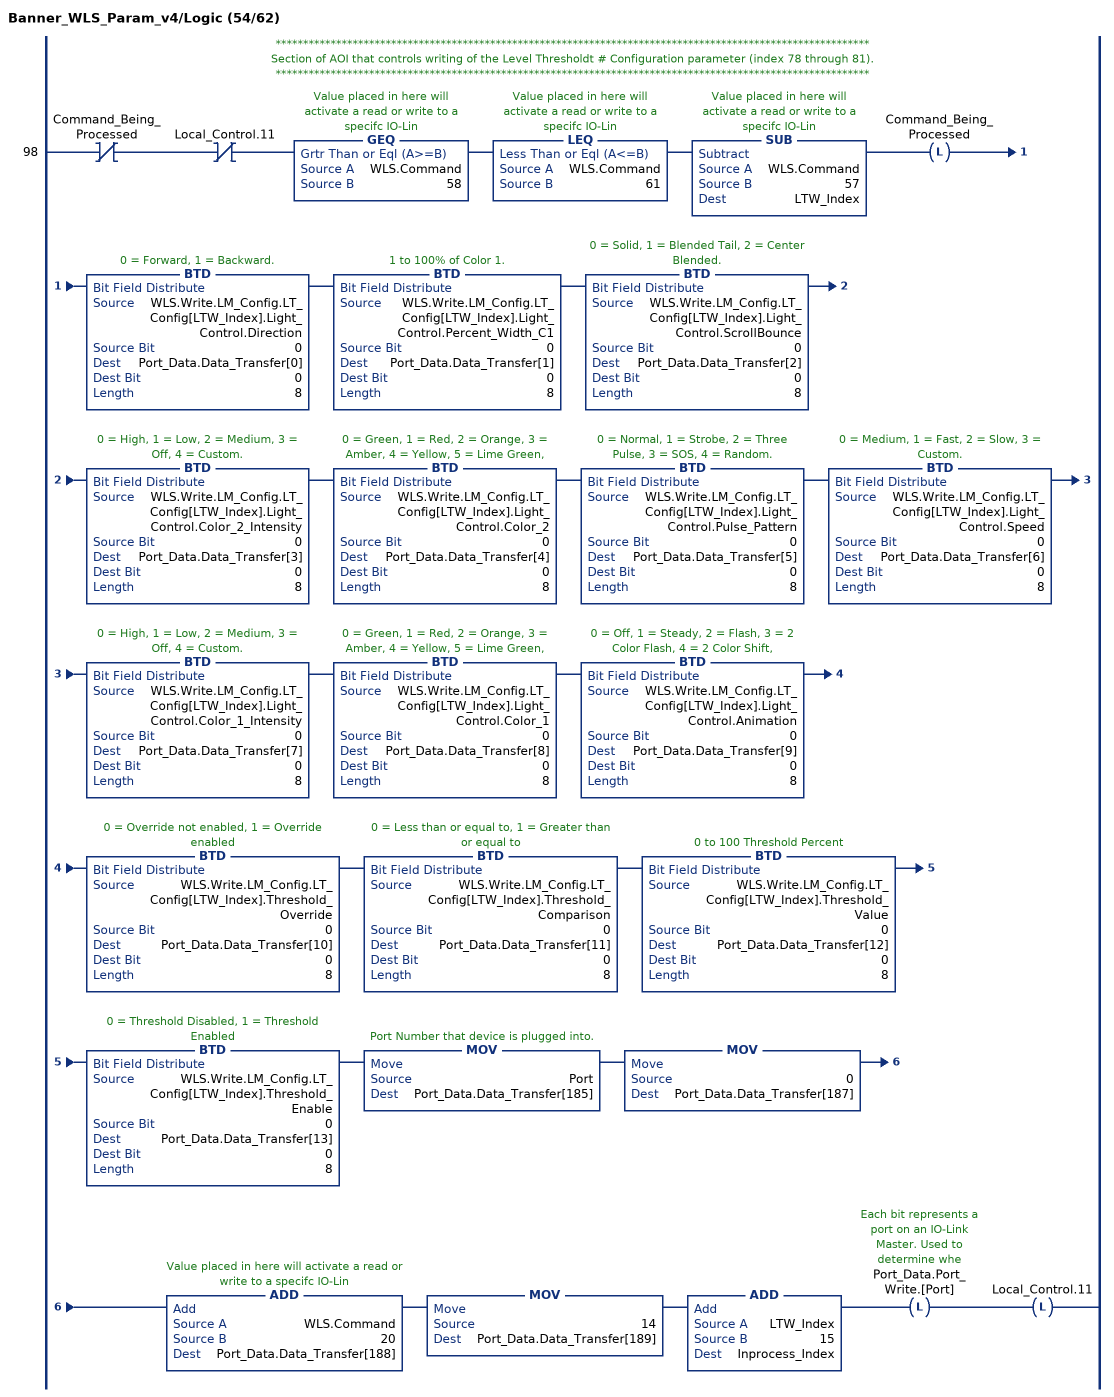
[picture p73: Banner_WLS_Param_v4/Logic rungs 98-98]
   // ************************************************************************************************************
   // Section of AOI that controls writing of the Level Thresholdt # Configuration parameter (index 78 through 81).
   // ************************************************************************************************************
   98: XIO(Command_Being_Processed)XIO(Local_Control.11)GEQ(WLS.Command,58)LEQ(WLS.Command,61)SUB(WLS.Command,57,LTW_Index)OTL(Command_Being_Processed)BTD(WLS.Write.LM_Config.LT_Config[LTW_Index].Light_Control.Direction,0,Port_Data.Data_Transfer[0],0,8)BTD(WLS.Write.LM_Config.LT_Config[LTW_Index].Light_Control.Percent_Width_C1,0,Port_Data.Data_Transfer[1],0,8)BTD(WLS.Write.LM_Config.LT_Config[LTW_Index].Light_Control.ScrollBounce,0,Port_Data.Data_Transfer[2],0,8)BTD(WLS.Write.LM_Config.LT_Config[LTW_Index].Light_Control.Color_2_Intensity,0,Port_Data.Data_Transfer[3],0,8)BTD(WLS.Write.LM_Config.LT_Config[LTW_Index].Light_Control.Color_2,0,Port_Data.Data_Transfer[4],0,8)BTD(WLS.Write.LM_Config.LT_Config[LTW_Index].Light_Control.Pulse_Pattern,0,Port_Data.Data_Transfer[5],0,8)BTD(WLS.Write.LM_Config.LT_Config[LTW_Index].Light_Control.Speed,0,Port_Data.Data_Transfer[6],0,8)BTD(WLS.Write.LM_Config.LT_Config[LTW_Index].Light_Control.Color_1_Intensity,0,Port_Data.Data_Transfer[7],0,8)BTD(WLS.Write.LM_Config.LT_Config[LTW_Index].Light_Control.Color_1,0,Port_Data.Data_Transfer[8],0,8)BTD(WLS.Write.LM_Config.LT_Config[LTW_Index].Light_Control.Animation,0,Port_Data.Data_Transfer[9],0,8)BTD(WLS.Write.LM_Config.LT_Config[LTW_Index].Threshold_Override,0,Port_Data.Data_Transfer[10],0,8)BTD(WLS.Write.LM_Config.LT_Config[LTW_Index].Threshold_Comparison,0,Port_Data.Data_Transfer[11],0,8)BTD(WLS.Write.LM_Config.LT_Config[LTW_Index].Threshold_Value,0,Port_Data.Data_Transfer[12],0,8)BTD(WLS.Write.LM_Config.LT_Config[LTW_Index].Threshold_Enable,0,Port_Data.Data_Transfer[13],0,8)MOV(Port,Port_Data.Data_Transfer[185])MOV(0,Port_Data.Data_Transfer[187])ADD(WLS.Command,20,Port_Data.Data_Transfer[188])MOV(14,Port_Data.Data_Transfer[189])ADD(LTW_Index,15,Inprocess_Index)OTL(Port_Data.Port_Write.[Port])OTL(Local_Control.11);
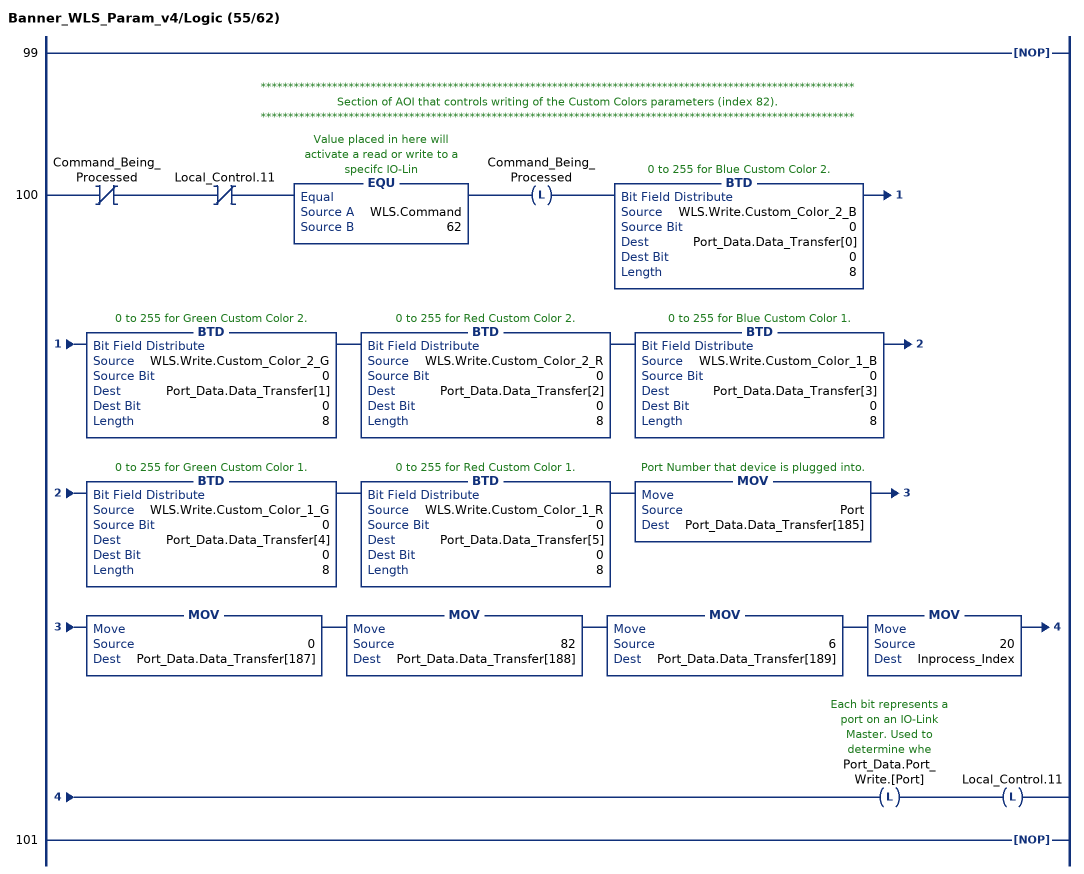
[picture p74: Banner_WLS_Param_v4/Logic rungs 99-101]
   99: NOP();
   // ************************************************************************************************************
   // Section of AOI that controls writing of the Custom Colors parameters (index 82).
   // ************************************************************************************************************
   100: XIO(Command_Being_Processed)XIO(Local_Control.11)EQU(WLS.Command,62)OTL(Command_Being_Processed)BTD(WLS.Write.Custom_Color_2_B,0,Port_Data.Data_Transfer[0],0,8)BTD(WLS.Write.Custom_Color_2_G,0,Port_Data.Data_Transfer[1],0,8)BTD(WLS.Write.Custom_Color_2_R,0,Port_Data.Data_Transfer[2],0,8)BTD(WLS.Write.Custom_Color_1_B,0,Port_Data.Data_Transfer[3],0,8)BTD(WLS.Write.Custom_Color_1_G,0,Port_Data.Data_Transfer[4],0,8)BTD(WLS.Write.Custom_Color_1_R,0,Port_Data.Data_Transfer[5],0,8)MOV(Port,Port_Data.Data_Transfer[185])MOV(0,Port_Data.Data_Transfer[187])MOV(82,Port_Data.Data_Transfer[188])MOV(6,Port_Data.Data_Transfer[189])MOV(20,Inprocess_Index)OTL(Port_Data.Port_Write.[Port])OTL(Local_Control.11);
   101: NOP();
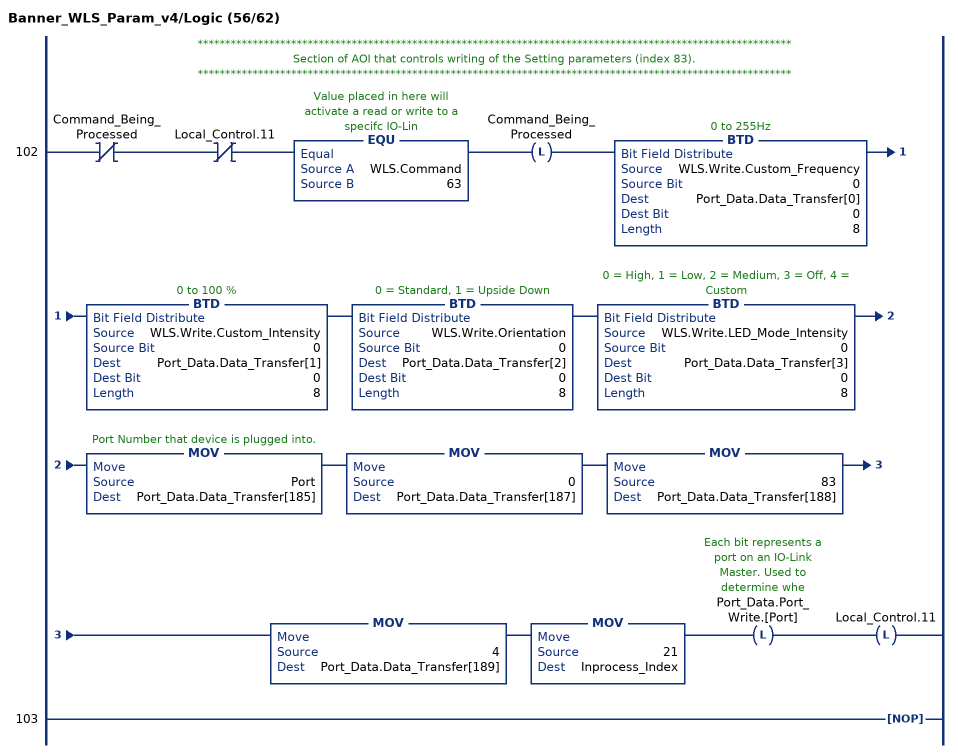
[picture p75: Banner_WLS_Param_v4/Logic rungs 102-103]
   // ************************************************************************************************************
   // Section of AOI that controls writing of the Setting parameters (index 83).
   // ************************************************************************************************************
   102: XIO(Command_Being_Processed)XIO(Local_Control.11)EQU(WLS.Command,63)OTL(Command_Being_Processed)BTD(WLS.Write.Custom_Frequency,0,Port_Data.Data_Transfer[0],0,8)BTD(WLS.Write.Custom_Intensity,0,Port_Data.Data_Transfer[1],0,8)BTD(WLS.Write.Orientation,0,Port_Data.Data_Transfer[2],0,8)BTD(WLS.Write.LED_Mode_Intensity,0,Port_Data.Data_Transfer[3],0,8)MOV(Port,Port_Data.Data_Transfer[185])MOV(0,Port_Data.Data_Transfer[187])MOV(83,Port_Data.Data_Transfer[188])MOV(4,Port_Data.Data_Transfer[189])MOV(21,Inprocess_Index)OTL(Port_Data.Port_Write.[Port])OTL(Local_Control.11);
   103: NOP();
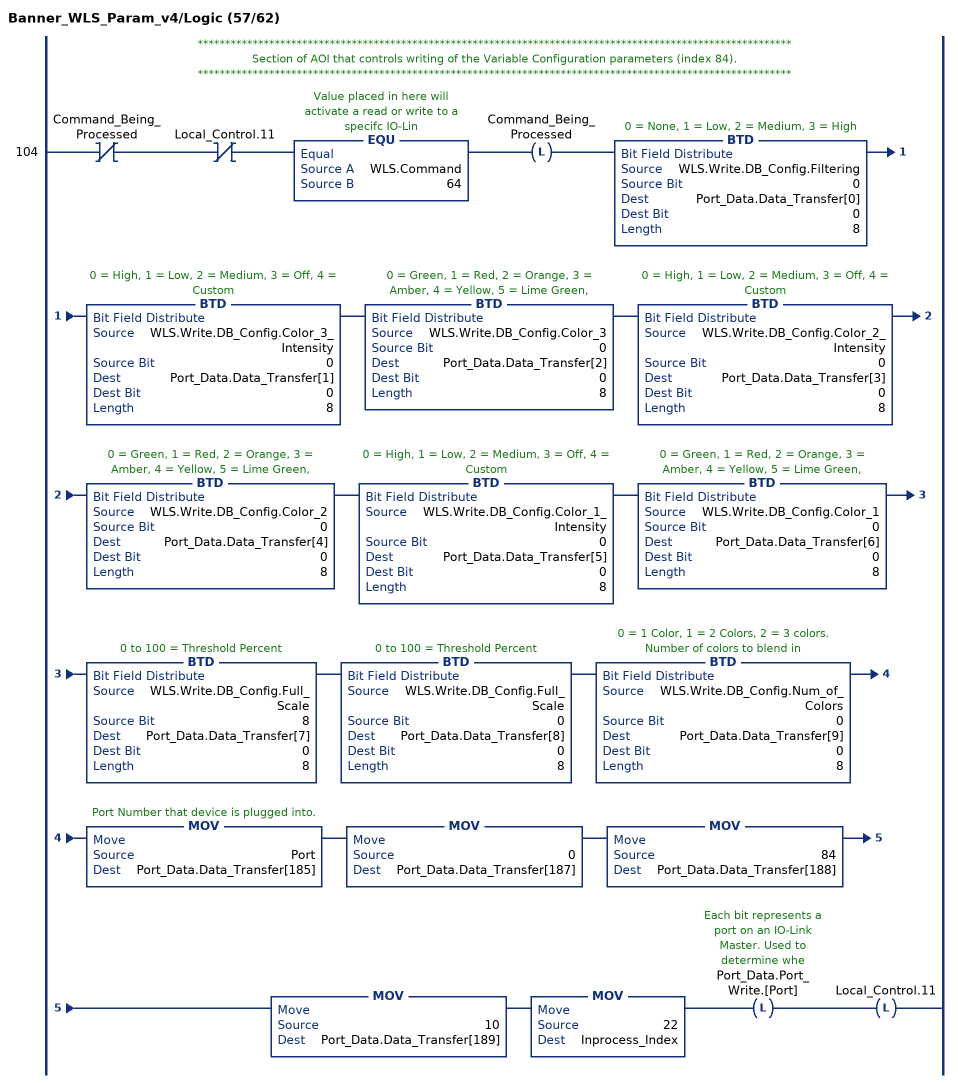
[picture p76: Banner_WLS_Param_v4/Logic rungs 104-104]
   // ************************************************************************************************************
   // Section of AOI that controls writing of the Variable Configuration parameters (index 84).
   // ************************************************************************************************************
   104: XIO(Command_Being_Processed)XIO(Local_Control.11)EQU(WLS.Command,64)OTL(Command_Being_Processed)BTD(WLS.Write.DB_Config.Filtering,0,Port_Data.Data_Transfer[0],0,8)BTD(WLS.Write.DB_Config.Color_3_Intensity,0,Port_Data.Data_Transfer[1],0,8)BTD(WLS.Write.DB_Config.Color_3,0,Port_Data.Data_Transfer[2],0,8)BTD(WLS.Write.DB_Config.Color_2_Intensity,0,Port_Data.Data_Transfer[3],0,8)BTD(WLS.Write.DB_Config.Color_2,0,Port_Data.Data_Transfer[4],0,8)BTD(WLS.Write.DB_Config.Color_1_Intensity,0,Port_Data.Data_Transfer[5],0,8)BTD(WLS.Write.DB_Config.Color_1,0,Port_Data.Data_Transfer[6],0,8)BTD(WLS.Write.DB_Config.Full_Scale,8,Port_Data.Data_Transfer[7],0,8)BTD(WLS.Write.DB_Config.Full_Scale,0,Port_Data.Data_Transfer[8],0,8)BTD(WLS.Write.DB_Config.Num_of_Colors,0,Port_Data.Data_Transfer[9],0,8)MOV(Port,Port_Data.Data_Transfer[185])MOV(0,Port_Data.Data_Transfer[187])MOV(84,Port_Data.Data_Transfer[188])MOV(10,Port_Data.Data_Transfer[189])MOV(22,Inprocess_Index)OTL(Port_Data.Port_Write.[Port])OTL(Local_Control.11);
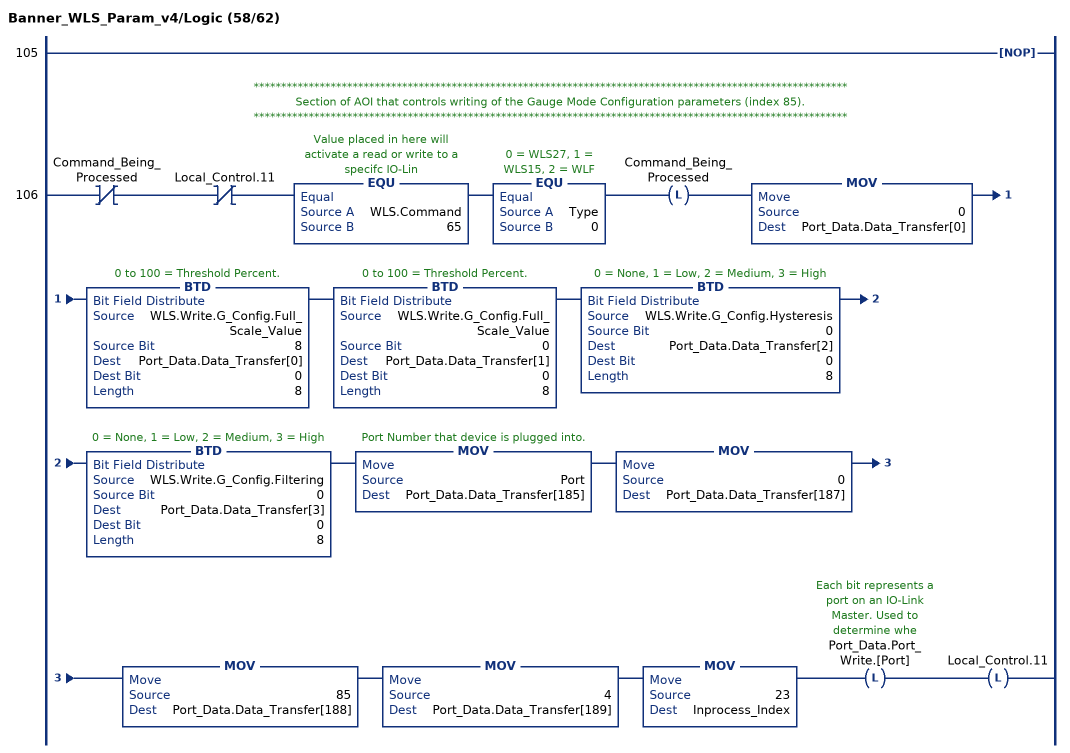
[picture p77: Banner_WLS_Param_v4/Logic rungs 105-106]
   105: NOP();
   // ************************************************************************************************************
   // Section of AOI that controls writing of the Gauge Mode Configuration parameters (index 85).
   // ************************************************************************************************************
   106: XIO(Command_Being_Processed)XIO(Local_Control.11)EQU(WLS.Command,65)EQU(Type,0)OTL(Command_Being_Processed)MOV(0,Port_Data.Data_Transfer[0])BTD(WLS.Write.G_Config.Full_Scale_Value,8,Port_Data.Data_Transfer[0],0,8)BTD(WLS.Write.G_Config.Full_Scale_Value,0,Port_Data.Data_Transfer[1],0,8)BTD(WLS.Write.G_Config.Hysteresis,0,Port_Data.Data_Transfer[2],0,8)BTD(WLS.Write.G_Config.Filtering,0,Port_Data.Data_Transfer[3],0,8)MOV(Port,Port_Data.Data_Transfer[185])MOV(0,Port_Data.Data_Transfer[187])MOV(85,Port_Data.Data_Transfer[188])MOV(4,Port_Data.Data_Transfer[189])MOV(23,Inprocess_Index)OTL(Port_Data.Port_Write.[Port])OTL(Local_Control.11);
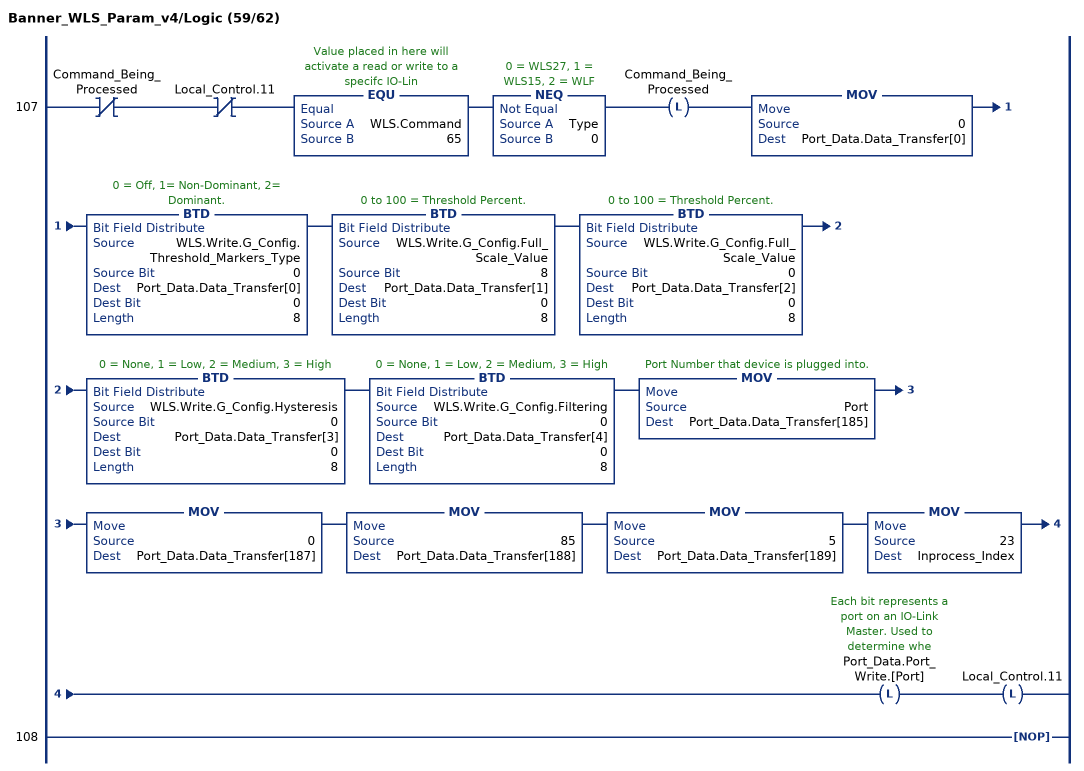
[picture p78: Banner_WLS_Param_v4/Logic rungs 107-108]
   107: XIO(Command_Being_Processed)XIO(Local_Control.11)EQU(WLS.Command,65)NEQ(Type,0)OTL(Command_Being_Processed)MOV(0,Port_Data.Data_Transfer[0])BTD(WLS.Write.G_Config.Threshold_Markers_Type,0,Port_Data.Data_Transfer[0],0,8)BTD(WLS.Write.G_Config.Full_Scale_Value,8,Port_Data.Data_Transfer[1],0,8)BTD(WLS.Write.G_Config.Full_Scale_Value,0,Port_Data.Data_Transfer[2],0,8)BTD(WLS.Write.G_Config.Hysteresis,0,Port_Data.Data_Transfer[3],0,8)BTD(WLS.Write.G_Config.Filtering,0,Port_Data.Data_Transfer[4],0,8)MOV(Port,Port_Data.Data_Transfer[185])MOV(0,Port_Data.Data_Transfer[187])MOV(85,Port_Data.Data_Transfer[188])MOV(5,Port_Data.Data_Transfer[189])MOV(23,Inprocess_Index)OTL(Port_Data.Port_Write.[Port])OTL(Local_Control.11);
   108: NOP();
